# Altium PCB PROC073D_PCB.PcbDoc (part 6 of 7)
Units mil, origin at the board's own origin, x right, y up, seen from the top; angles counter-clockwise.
Board outline 2165.35 x 2695.12 mil, 8 copper layers (Top Layer, L2_GND, L3_SIGNAL 1, L4_SIGNAL 2, L5_SIGNAL 3, L6_SIGNAL 4, L7_GND, Bottom Layer), stack 56.1 mil thick; 414 components, 319 nets, 1353 pads, 1669 vias.
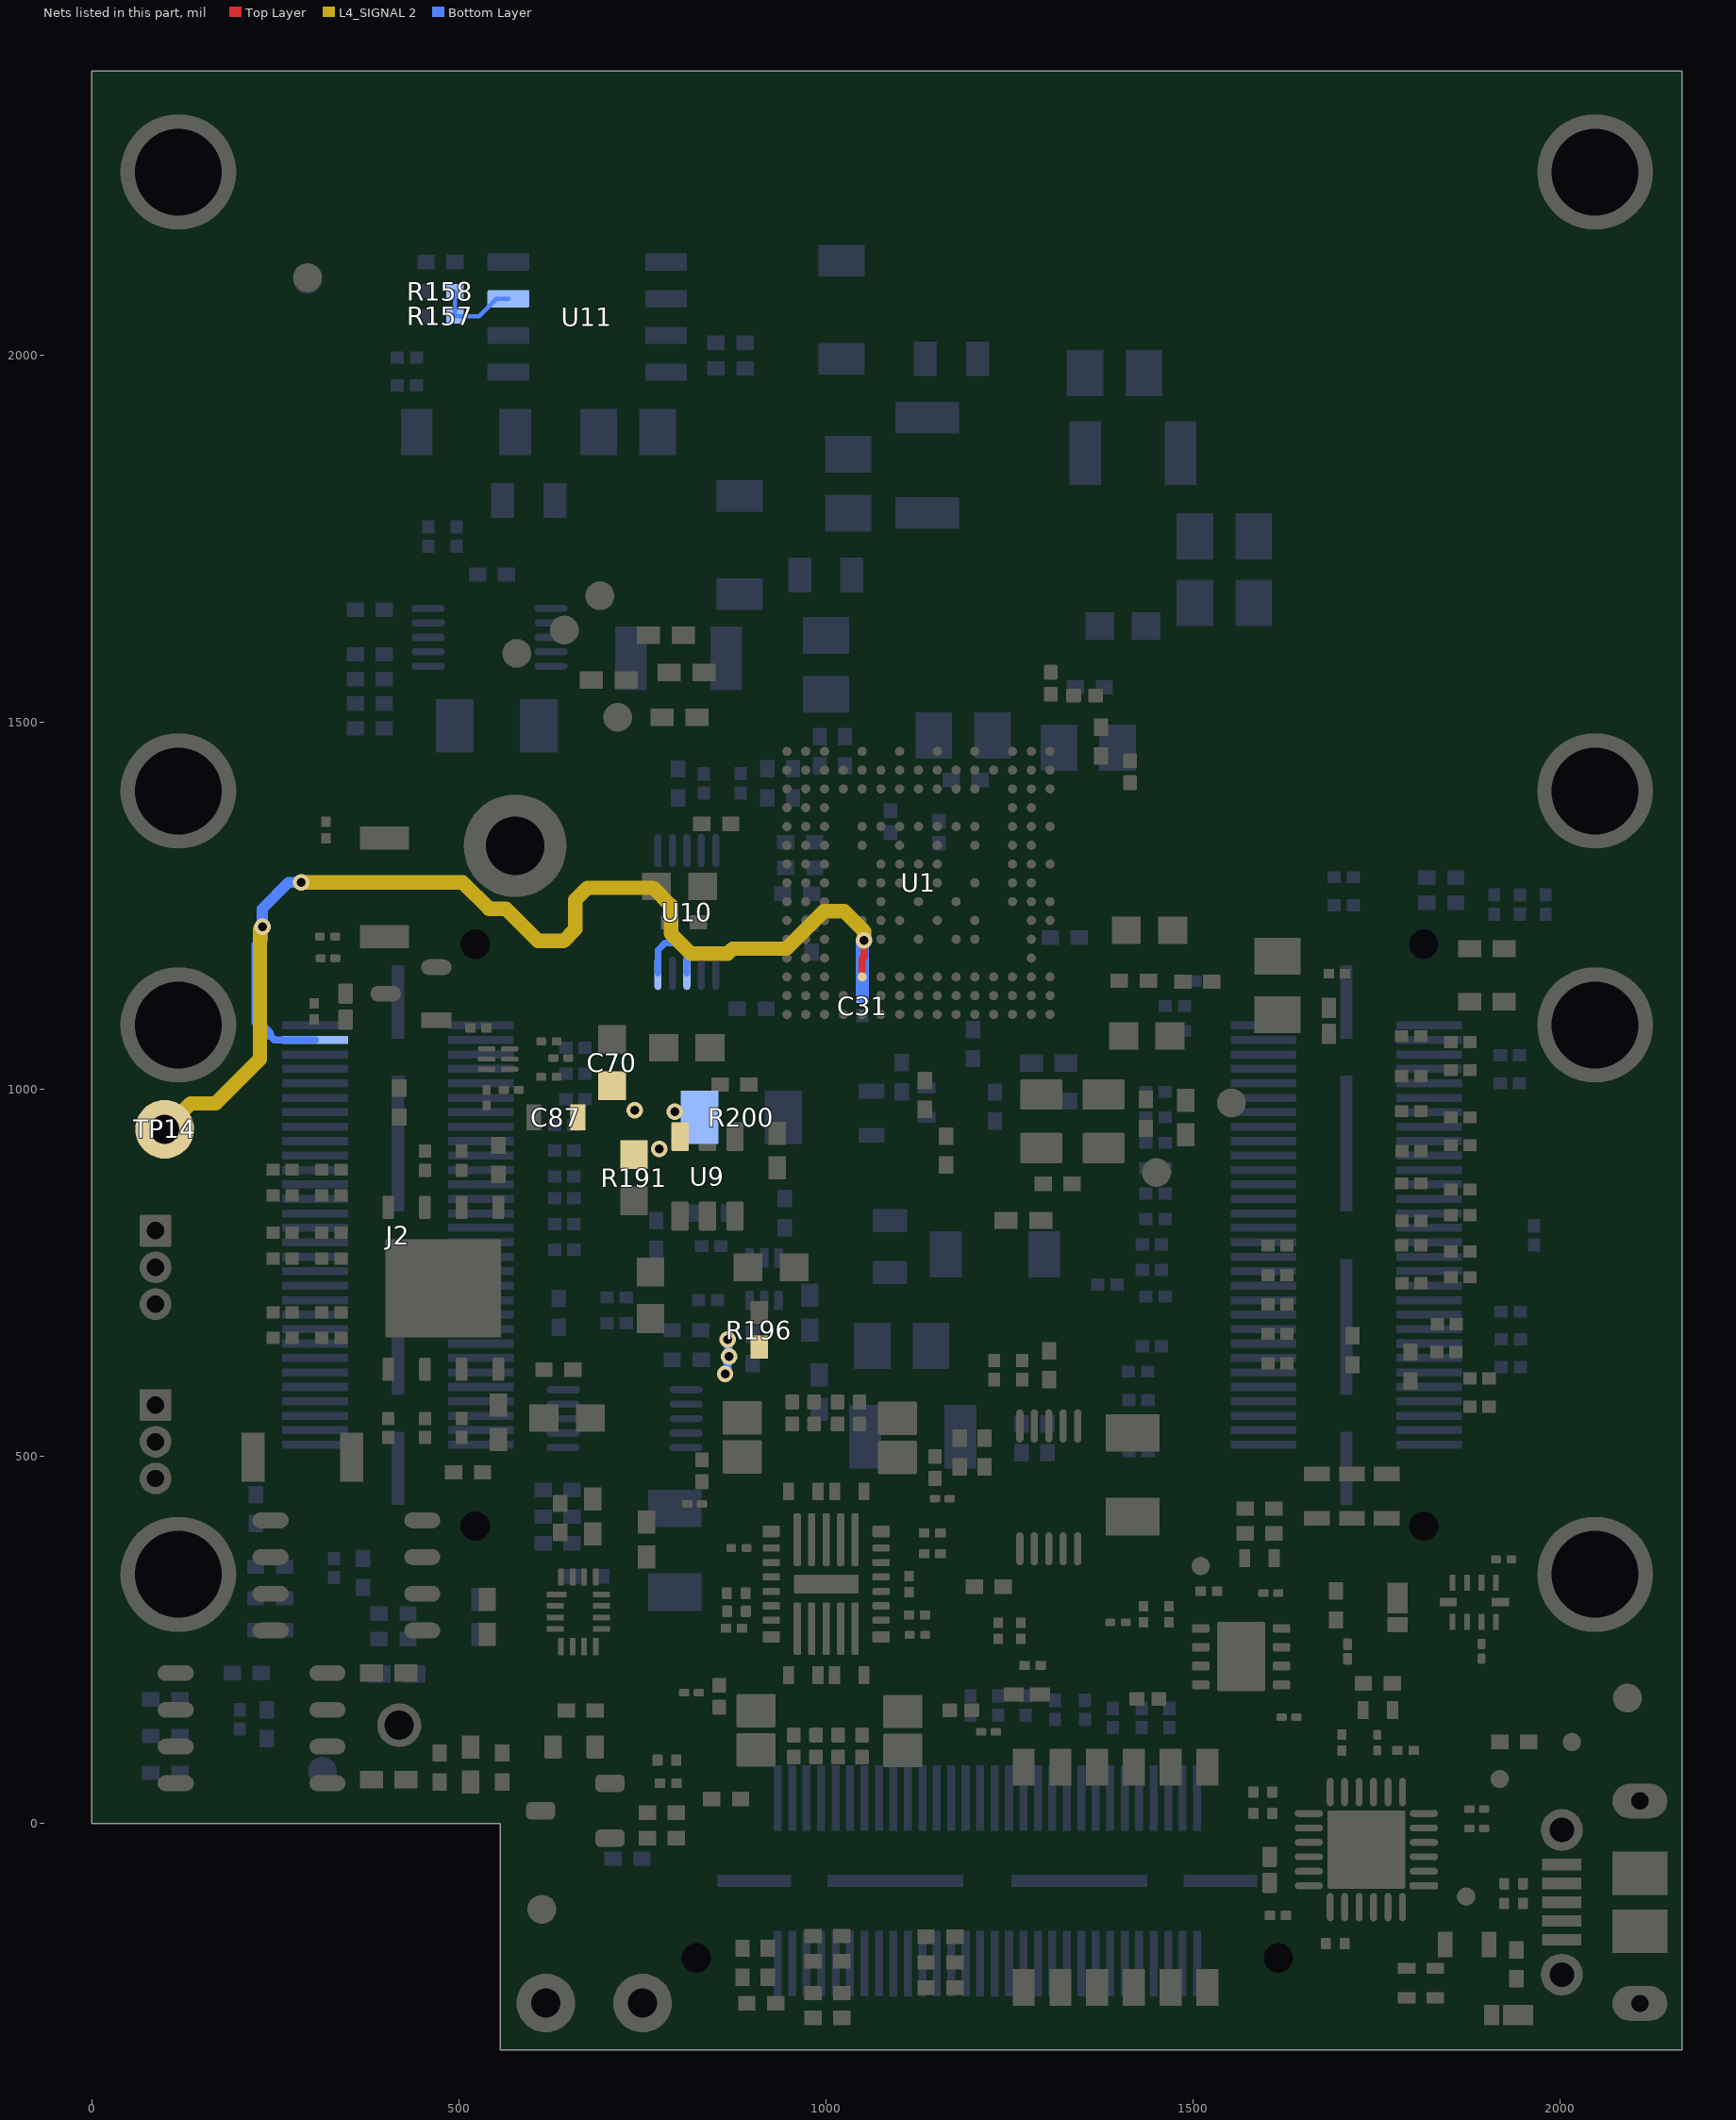
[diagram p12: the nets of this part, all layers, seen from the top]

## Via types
v1: diameter 13.77/15.74 (per signal layer), hole 5.9, Top Layer to L2_GND, tented both sides, 900 vias
v2: diameter 22.4, hole 12.2, Top Layer to Bottom Layer, tented both sides, 509 vias
v3: diameter 13.78/15.75 (per signal layer), hole 5.9, Top Layer to L2_GND, tented both sides, 72 vias
v4: diameter 18, hole 8, Top Layer to Bottom Layer, tented both sides, 71 vias
v5: diameter 22, hole 12.2, Top Layer to Bottom Layer, tented both sides, 57 vias
v6: diameter 25, hole 15, Top Layer to Bottom Layer, tented both sides, 28 vias
v7: diameter 19.68, hole 7.87, Top Layer to Bottom Layer, 16 vias
v8: diameter 13.77/15.74 (per signal layer), hole 5.9, Top Layer to L2_GND, tented top, 15 vias
v9: diameter 13.78/15.75 (per signal layer), hole 5.9, Top Layer to L2_GND, tented top, 1 vias

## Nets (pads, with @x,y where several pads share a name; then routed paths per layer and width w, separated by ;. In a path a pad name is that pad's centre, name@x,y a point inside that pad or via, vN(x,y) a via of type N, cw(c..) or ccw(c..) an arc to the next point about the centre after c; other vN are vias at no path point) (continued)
VCC_LD_SW_3V3: C70.1 C87.2 R191.2 R196.1 R200.1 U9.6 U10.8 U10.10 | length 160.9
  Bottom Layer w9: U10.10@771.22,1157.77 771.22,1189.43 781.22,1199.43 800.59,1199.43 810.59,1189.43 U10.8@810.59,1157.77
  Bottom Layer w12: v2(862.61,612.42) 865.79,615.6 865.79,633.91 v2(868.15,636.27) 867.13,637.29 867.13,658.2 v2(866.15,659.18)
  other v2: 773.12,918.67 794.01,969.55 739.62,971.31
VPP_1P7: C31.2 J2.57 TP14.1 U1.L13 | length 1753.3
  Top Layer w10: U1.L13@1049.21,1153.09 1049.2,1177.77 1052.02,1180.59 v2(1052.02,1202.49)
  L4_SIGNAL 2 w19.68: TP14.1@99.51,945.49 134.85,980.83 169.16,980.83 229.24,1040.91 229.24,1217.81 v2(232.52,1221.08) ; v2(285.39,1281.6) 505.38,1281.6 541.2,1245.78 564.17,1245.78 607.94,1202.01 642.73,1202.01 658.57,1217.85 658.57,1257.88 675.05,1274.36 764.73,1274.36 789.03,1250.06 789.03,1212.15 816.54,1184.65 865.97,1184.65 872.79,1191.47 946.19,1191.47 997.06,1242.33 1024.8,1242.33 1052.02,1215.11 v2(1052.02,1202.49)
  Bottom Layer w10: 241.12,1075.3 249.25,1067.18 J2.57@304.44,1067.18
  Bottom Layer w15: 241.12,1075.3 225,1091.43 225,1196.18 232.52,1203.7 v2(232.52,1221.08) 232.52,1245.87 268.24,1281.6 v2(285.39,1281.6)
  Bottom Layer w18: C31.2@1049.59,1126.42 1049.59,1200.05 v2(1052.02,1202.49)
WP#: R157.1 R158.2 U11.7 | length 117
  Bottom Layer w6: R158.2@494.69,2086.43 R157.1@494.69,2052.43 527.59,2052.43 551.59,2076.43 U11.7@567.72,2076.43
pads on no net: FID1.1 FID2.1 FID3.1 FID4.1 FID5.1 FID6.1 J1.MH1 J1.MH2 J2.1 J2.2 J2.3 J2.4 J2.5 J2.6 J2.7 J2.8 J2.9 J2.10 J2.11 J2.12 J2.13 J2.14 J2.15 J2.16 J2.17 J2.18 J2.20 J2.22 J2.24 J2.26 J2.33 J2.35 J2.45 J2.47 J2.49 J2.51 J2.53 J2.55 J2.MH1 J2.MH2 J5.4 J6.4 J6.5 J6.6 J6.8 J6.14 J6.MH1 J6.MH2 LBL1.0 S1.6 S1.7 U2. U4. U11.1 U11.2 U14.10 U14.11 U14.14 U14.15 U14.16 U14.18 U14.19 U14.21 U14.22 U14.23 U14.24 U16.9@1565.35,202.73 U16.9@1565.35,252.34

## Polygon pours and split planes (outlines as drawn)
GND on Top Layer "GND_L01_P43637" (solid, remove dead copper, pour order 43637): 19 vertices, not listed, extent 1626.69,448.97 1824.73,644.12
VCC_3V3 on Top Layer " " (solid, remove dead copper, pour order 43574): 864.52,29.48 858.08,23.04 818.23,23.04 818.23,87.88 864.52,87.88
PMIC_1V2 on Top Layer "Bottom Layer-PMIC_1V2" (solid, pour order 43628): 1176.88,139.67 1176.88,51.5 1006.53,51.49 1006.53,139.67
PMIC_3V3 on Top Layer "Bottom Layer-PMIC_3V3" (solid, pour order 43625): 17 vertices, not listed, extent 869.49,21.76 996.5,123.71
GND on Top Layer "GND_L01_P43638" (solid, remove dead copper, pour order 43638): 24 vertices, not listed, extent 1134.79,114.97 1434.22,281.92
SW2_CAP on Top Layer "SW2_CAP_L01_P43547" (solid, remove dead copper, pour order 43547): 823.81,445.71 819.76,449.76 819.76,475.41 822.6,478.25 840.37,478.25 843.87,474.75 843.87,428.59 840.67,425.39 826.75,425.39 823.81,428.34
GND on Top Layer "TOP-No Net" (solid, remove dead copper, pour order 43644): 848.74,2365.39 667.78,2365.74 667.7,1749.46 727.62,1689.54 846.06,1689.54 848.74,1692.21
GND on Top Layer "TOP-No Net" (solid, remove dead copper, pour order 43640): 1976.7,2327.43 1976.77,2365.35 809.74,2365.49 809.74,2327.43
GND on Top Layer "TOP-No Net" (solid, remove dead copper, pour order 43645): 1940.79,2365.31 2139.97,2365.71 2140.06,1608.43 1940.79,1608.42
GND on Top Layer "GND_L01_P448" (solid, remove dead copper, pour order 43648): 32 vertices, not listed, extent 31,1195.43 2140.01,2365.48
GND on Top Layer "TOP-No Net 11" (solid, remove dead copper, pour order 43612): 94 vertices, not listed, extent 996.99,1670.75 1095.41,2143.74
GND on Top Layer "TOP-No Net 17" (solid, remove dead copper, pour order 43611): 94 vertices, not listed, extent 1193.85,1670.75 1292.27,2143.74
GND on Top Layer "OUTLINE-No Net" (solid, remove dead copper, pour order 43564): 1787.47,1737.78 1787.47,1682.49 1805.98,1682.49 1805.98,1670.77 1821.73,1670.77 1821.73,1698.24 1803.22,1698.24 1803.22,1722.03 1821.73,1722.03 1821.73,1762.89 1805.98,1762.89 1805.98,1737.78 1787.47,1737.78
TX3 on Top Layer "TOP-RX1 72" (solid, pour order 43525): 1835.62,1941.12 1831.62,1941.12 1831.62,1880.57 1835.62,1880.57 1835.62,1941.12
GND on Top Layer "OUTLINE-No Net" (solid, remove dead copper, pour order 43557): 1894.77,2143.76 1772.47,2143.76 1772.47,2128.01 1894.77,2128.01 1894.77,2143.76
TX3 on Top Layer "TOP-RX1 73" (solid, pour order 43524): 1835.62,2049.7 1831.62,2049.7 1831.62,1989.15 1835.62,1989.15 1835.62,2049.7
GND on Top Layer "TOP-GND 25" (solid, remove dead copper, pour order 43545): 1894.77,1802.26 1845.52,1802.26 1845.52,1786.52 1894.77,1786.52
TX3 on Top Layer "TOP-RX1 74" (solid, pour order 43527): 1837.52,1762.89 1829.73,1762.89 1829.73,1724.7 1837.52,1724.7 1837.52,1762.89
GND on Top Layer "OUTLINE-No Net" (solid, remove dead copper, pour order 43543): 1821.73,1802.26 1772.47,1802.26 1772.47,1786.52 1821.73,1786.52 1821.73,1802.26
TX3 on Top Layer "TOP-RX1 75" (solid, pour order 43513): 1837.52,1724.7 1829.73,1724.7 1829.73,1710.14 1837.52,1710.14 1837.52,1724.7
GND on Top Layer "OUTLINE-No Net" (solid, remove dead copper, pour order 43535): 1821.73,1786.52 1805.98,1786.52 1805.98,1762.89 1821.73,1762.89 1821.73,1786.52
TX3 on Top Layer "TOP-RX1 76" (solid, pour order 43509): 1850.51,1728.6 1837.52,1728.6 1837.52,1720.81 1850.51,1720.81 1850.51,1728.6
GND on Top Layer "TOP-GND 26" (solid, remove dead copper, pour order 43540): 1861.27,1786.52 1845.52,1786.52 1845.52,1762.89 1861.27,1762.89 1861.27,1786.52
TX3 on Top Layer "TOP-RX1 77" (solid, pour order 43567): 1859.21,1880.57 1808.03,1880.57 1808.03,1832.54 1859.21,1832.54 1859.21,1880.57
GND on Top Layer "TOP-GND 27" (solid, remove dead copper, pour order 43554): 1861.27,1762.89 1845.52,1762.89 1845.52,1736.6 1858.51,1736.6 1858.51,1712.81 1845.52,1712.81 1845.52,1670.77 1861.27,1670.77 1861.27,1697.06 1874.26,1697.06 1874.26,1752.35 1861.27,1752.35 1861.27,1762.89
TX3 on Top Layer "TOP-RX1 78" (solid, pour order 43532): 1837.52,1802.26 1829.73,1802.26 1829.73,1762.89 1837.52,1762.89 1837.52,1802.26
TX3 on Top Layer "TOP-RX1 79" (solid, pour order 43514): 1835.62,1832.54 1831.62,1832.54 1831.62,1802.26 1835.62,1802.26 1835.62,1832.54
TX3 on Top Layer "TOP-RX1 80" (solid, pour order 43518): 1829.73,1714.03 1811.22,1714.03 1811.22,1706.24 1829.73,1706.24 1829.73,1714.03
TX3 on Top Layer "TOP-RX1 81" (solid, pour order 43579): 1871.03,1989.15 1796.22,1989.15 1796.22,1941.12 1871.03,1941.12 1871.03,1989.15
GND on Top Layer "OUTLINE-No Net" (solid, remove dead copper, pour order 43589): 1788.22,2128.01 1772.47,2128.01 1772.47,1802.26 1788.22,1802.26 1788.22,2128.01
TX3 on Top Layer "TOP-RX1 83" (solid, pour order 43568): 1859.21,2097.74 1808.03,2097.74 1808.03,2049.7 1859.21,2049.7 1859.21,2097.74
GND on Top Layer "OUTLINE-No Net" (solid, remove dead copper, pour order 43585): 1894.77,2128.01 1879.03,2128.01 1879.03,1802.26 1894.77,1802.26 1894.77,2128.01
GND on Top Layer "OUTLINE-No Net" (solid, remove dead copper, pour order 43590): 1697.92,2226.44 1682.17,2226.44 1682.17,1900.69 1697.92,1900.69 1697.92,2226.44
TX2 on Top Layer "TOP-RX1 83" (solid, pour order 43571): 1662.36,2196.16 1611.18,2196.16 1611.18,2148.13 1662.36,2148.13 1662.36,2196.16
GND on Top Layer "OUTLINE-No Net" (solid, remove dead copper, pour order 43587): 1591.37,2226.44 1575.62,2226.44 1575.62,1900.69 1591.37,1900.69 1591.37,2226.44
TX2 on Top Layer "TOP-RX1 81" (solid, pour order 43578): 1674.17,2087.58 1599.37,2087.58 1599.37,2039.55 1674.17,2039.55 1674.17,2087.58
TX2 on Top Layer "TOP-RX1 80" (solid, pour order 43517): 1632.88,1812.46 1614.37,1812.46 1614.37,1804.66 1632.88,1804.66 1632.88,1812.46
TX2 on Top Layer "TOP-RX1 79" (solid, pour order 43516): 1638.77,1930.96 1634.77,1930.96 1634.77,1900.69 1638.77,1900.69 1638.77,1930.96
TX2 on Top Layer "TOP-RX1 78" (solid, pour order 43531): 1640.67,1900.69 1632.88,1900.69 1632.88,1861.32 1640.67,1861.32 1640.67,1900.69
TX2 on Top Layer "TOP-RX1 77" (solid, pour order 43566): 1662.36,1979 1611.18,1979 1611.18,1930.96 1662.36,1930.96 1662.36,1979
GND on Top Layer "TOP-GND 26" (solid, remove dead copper, pour order 43536): 1664.42,1884.94 1648.67,1884.94 1648.67,1861.32 1664.42,1861.32 1664.42,1884.94
TX2 on Top Layer "TOP-RX1 76" (solid, pour order 43508): 1653.66,1827.03 1640.67,1827.03 1640.67,1819.23 1653.66,1819.23 1653.66,1827.03
GND on Top Layer "OUTLINE-No Net" (solid, remove dead copper, pour order 43538): 1624.88,1884.94 1609.13,1884.94 1609.13,1861.32 1624.88,1861.32 1624.88,1884.94
TX2 on Top Layer "TOP-RX1 75" (solid, pour order 43512): 1640.67,1823.13 1632.88,1823.13 1632.88,1808.56 1640.67,1808.56 1640.67,1823.13
GND on Top Layer "OUTLINE-No Net" (solid, remove dead copper, pour order 43542): 1624.88,1900.69 1575.62,1900.69 1575.62,1884.94 1624.88,1884.94 1624.88,1900.69
TX2 on Top Layer "TOP-RX1 74" (solid, pour order 43526): 1640.67,1861.32 1632.88,1861.32 1632.88,1823.13 1640.67,1823.13 1640.67,1861.32
GND on Top Layer "TOP-GND 25" (solid, remove dead copper, pour order 43546): 1697.92,1900.69 1648.67,1900.69 1648.67,1884.94 1697.92,1884.94 1697.92,1900.69
TX2 on Top Layer "TOP-RX1 73" (solid, pour order 43520): 1638.77,2148.13 1634.77,2148.13 1634.77,2087.58 1638.77,2087.58 1638.77,2148.13
GND on Top Layer "OUTLINE-No Net" (solid, remove dead copper, pour order 43556): 1697.92,2242.18 1575.62,2242.18 1575.62,2226.44 1697.92,2226.44 1697.92,2242.18
TX2 on Top Layer "TOP-RX1 72" (solid, pour order 43522): 1638.77,2039.55 1634.77,2039.55 1634.77,1979 1638.77,1979 1638.77,2039.55
GND on Top Layer "OUTLINE-No Net" (solid, remove dead copper, pour order 43563): 1393.77,1737.78 1393.77,1682.49 1412.28,1682.49 1412.28,1670.77 1428.03,1670.77 1428.03,1698.24 1409.52,1698.24 1409.52,1722.03 1428.03,1722.03 1428.03,1762.89 1412.28,1762.89 1412.28,1737.78 1393.77,1737.78
TX1 on Top Layer "TOP-RX1 72" (solid, pour order 43523): 1441.92,1941.12 1437.92,1941.12 1437.92,1880.57 1441.92,1880.57 1441.92,1941.12
GND on Top Layer "OUTLINE-No Net" (solid, remove dead copper, pour order 43558): 1501.07,2143.76 1378.77,2143.76 1378.77,2128.01 1501.07,2128.01 1501.07,2143.76
TX1 on Top Layer "TOP-RX1 73" (solid, pour order 43521): 1441.92,2049.7 1437.92,2049.7 1437.92,1989.15 1441.92,1989.15 1441.92,2049.7
GND on Top Layer "TOP-GND 25" (solid, remove dead copper, pour order 43544): 1501.07,1802.26 1451.82,1802.26 1451.82,1786.52 1501.07,1786.52 1501.07,1802.26
TX1 on Top Layer "TOP-RX1 74" (solid, pour order 43528): 1443.82,1762.89 1436.03,1762.89 1436.03,1724.7 1443.82,1724.7 1443.82,1762.89
GND on Top Layer "OUTLINE-No Net" (solid, remove dead copper, pour order 43541): 1428.03,1802.26 1378.77,1802.26 1378.77,1786.52 1428.03,1786.52 1428.03,1802.26
TX1 on Top Layer "TOP-RX1 75" (solid, pour order 43511): 1443.82,1724.7 1436.03,1724.7 1436.03,1710.14 1443.82,1710.14 1443.82,1724.7
GND on Top Layer "OUTLINE-No Net" (solid, remove dead copper, pour order 43537): 1428.03,1786.52 1412.28,1786.52 1412.28,1762.89 1428.03,1762.89 1428.03,1786.52
TX1 on Top Layer "TOP-RX1 76" (solid, pour order 43510): 1456.81,1728.6 1443.82,1728.6 1443.82,1720.81 1456.81,1720.81 1456.81,1728.6
GND on Top Layer "TOP-GND 26" (solid, remove dead copper, pour order 43539): 1467.57,1786.52 1451.82,1786.52 1451.82,1762.89 1467.57,1762.89 1467.57,1786.52
TX1 on Top Layer "TOP-RX1 77" (solid, pour order 43569): 1465.51,1880.57 1414.33,1880.57 1414.33,1832.54 1465.51,1832.54 1465.51,1880.57
GND on Top Layer "TOP-GND 27" (solid, remove dead copper, pour order 43555): 1467.57,1762.89 1451.82,1762.89 1451.82,1736.6 1464.81,1736.6 1464.81,1712.81 1451.82,1712.81 1451.82,1670.77 1467.57,1670.77 1467.57,1697.06 1480.56,1697.06 1480.56,1752.35 1467.57,1752.35 1467.57,1762.89
TX1 on Top Layer "TOP-RX1 78" (solid, pour order 43530): 1443.82,1802.26 1436.03,1802.26 1436.03,1762.89 1443.82,1762.89 1443.82,1802.26
TX1 on Top Layer "TOP-RX1 79" (solid, pour order 43515): 1441.92,1832.54 1437.92,1832.54 1437.92,1802.26 1441.92,1802.26 1441.92,1832.54
TX1 on Top Layer "TOP-RX1 80" (solid, pour order 43519): 1436.03,1714.03 1417.52,1714.03 1417.52,1706.24 1436.03,1706.24 1436.03,1714.03
TX1 on Top Layer "TOP-RX1 81" (solid, pour order 43580): 1477.32,1989.15 1402.52,1989.15 1402.52,1941.12 1477.32,1941.12 1477.32,1989.15
GND on Top Layer "OUTLINE-No Net" (solid, remove dead copper, pour order 43586): 1394.52,2128.01 1378.77,2128.01 1378.77,1802.26 1394.52,1802.26 1394.52,2128.01
TX1 on Top Layer "TOP-RX1 83" (solid, pour order 43570): 1465.51,2097.74 1414.33,2097.74 1414.33,2049.7 1465.51,2049.7 1465.51,2097.74
GND on Top Layer "OUTLINE-No Net" (solid, remove dead copper, pour order 43588): 1501.07,2128.01 1485.32,2128.01 1485.32,1802.26 1501.07,1802.26 1501.07,2128.01
GND on Top Layer "TOP-No Net 10" (solid, remove dead copper, pour order 43613): 94 vertices, not listed, extent 1095.42,1670.75 1193.84,2143.74
GND on Top Layer "TOP-No Net 23" (solid, remove dead copper, pour order 43623): 125 vertices, not listed, extent 891.67,1670.75 996.98,2143.74
GND on Top Layer "TOP-No Net 24" (solid, pour order 43550): 35 vertices, not listed, extent 1292.28,1786.55 1299.17,2143.74
RX1 on Top Layer "TOP-No Net 43" (solid, remove dead copper, pour order 43620): 38 vertices, not listed, extent 910.37,1670.75 985.17,2097.72
RX2 on Top Layer "TOP-No Net 42" (solid, remove dead copper, pour order 43617): 38 vertices, not listed, extent 1008.8,1670.75 1083.6,2097.72
RX3 on Top Layer "TOP-No Net 41" (solid, remove dead copper, pour order 43618): 38 vertices, not listed, extent 1107.23,1670.75 1182.03,2097.72
RX4 on Top Layer "TOP-No Net 40" (solid, remove dead copper, pour order 43619): 38 vertices, not listed, extent 1205.66,1670.75 1280.46,2097.72
TX1 on Top Layer "TOP-RX1 82" (solid, remove dead copper, pour order 43534): 1443.82,1710.14 1436.03,1710.14 1436.03,1670.77 1443.82,1670.77 1443.82,1710.14
GND on Top Layer "OUTLINE-No Net" (solid, remove dead copper, pour order 43562): 1590.62,1836.21 1590.62,1780.92 1609.13,1780.92 1609.13,1769.19 1624.88,1769.19 1624.88,1796.66 1606.37,1796.66 1606.37,1820.46 1624.88,1820.46 1624.88,1861.32 1609.13,1861.32 1609.13,1836.21 1590.62,1836.21
GND on Top Layer "TOP-GND 27" (solid, remove dead copper, pour order 43553): 1664.42,1861.32 1648.67,1861.32 1648.67,1835.03 1661.66,1835.03 1661.66,1811.23 1648.67,1811.23 1648.67,1769.19 1664.42,1769.19 1664.42,1795.48 1677.41,1795.48 1677.41,1850.77 1664.42,1850.77 1664.42,1861.32
TX2 on Top Layer "TOP-RX1 82" (solid, remove dead copper, pour order 43533): 1640.67,1808.56 1632.88,1808.56 1632.88,1769.19 1640.67,1769.19 1640.67,1808.56
TX3 on Top Layer "TOP-RX1 82" (solid, remove dead copper, pour order 43529): 1837.52,1710.14 1829.73,1710.14 1829.73,1670.77 1837.52,1670.77 1837.52,1710.14
PMICOUT_3V3 on Top Layer "PMICOUT_3V3_L01_P43548" (solid, remove dead copper, pour order 43548): 1888.11,267 1884.01,262.9 1884.01,240.03 1890.12,233.93 1918.25,233.93 1923.94,239.61 1923.94,251.86 1913.18,262.62 1906,262.62 1896.94,271.69 1896.94,287.72 1888.11,287.72
GND on Top Layer "GND_L01_P43647" (solid, remove dead copper, pour order 43647): 17 vertices, not listed, extent 30,241.44 226,2365.43
VCC_3V3 on Top Layer "TOP-No Net 1" (solid, remove dead copper, pour order 43646): 49 vertices, not listed, extent 41.47,164.01 885.63,871.43
CONN_5V on Top Layer "CONN_5V_L01_P43643" (solid, remove dead copper, pour order 43643): 1070.98,23.91 1087.57,40.5 1238.25,40.5 1249.82,28.92 1570.7,28.92 1604.25,-4.63 1604.25,-153.18 1564.44,-192.99 1380.08,-192.99 1330.58,-143.49 1251.49,-143.49 1206.02,-98.02 1081.74,-98.02 1070.98,-87.26
GND on Top Layer "TOP-No Net 1" (solid, remove dead copper, pour order 43642): 43 vertices, not listed, extent 573.85,531.61 806.04,1124.49
CB_PMIC_1V8 on Top Layer "CB_PMIC_1V8_L01_P43641" (solid, remove dead copper, pour order 43641): 21 vertices, not listed, extent 1305.39,336.57 1707.37,617.51
PMICOUT_3V3 on Top Layer "PMICOUT_3V3_L01_P43639" (solid, remove dead copper, pour order 43639): 26 vertices, not listed, extent 1236.39,31.5 1710.68,184.93
CONN_5V on Top Layer "CONN_5V_L01_P43636" (solid, remove dead copper, pour order 43636): 24 vertices, not listed, extent 1593.74,258.91 1865.7,505.35
PMIC_1V8 on Top Layer "Bottom Layer-PMIC_1V8" (solid, pour order 43635): 1004.7,631.77 1041.77,631.77 1044.89,632.39 1047.54,634.16 1073.58,660.2 1168.05,660.2 1189.28,638.97 1189.28,529.14 1068.83,529.14 1068.83,562.56 1004.71,562.56 1004.71,577.43
5V_IN_USB on Top Layer "5V_IN_USB_L01_P43634" (solid, remove dead copper, pour order 43634): 1867.12,-213.4 1887,-193.52 1902.36,-193.52 1914.38,-205.54 1914.38,-276.86 1906.59,-284.65 1679.89,-284.64 1664.98,-269.73 1664.98,-217.76 1678.81,-203.93 1761.64,-203.93 1771.11,-213.4
VCC_LD_SW_3V3 on Top Layer "TOP-No Net 1" (solid, remove dead copper, pour order 43633): 650.73,926.93 656.93,920.73 691.29,920.73 721,891.01 788.48,891.43 788.74,891.43 813.74,916.43 813.74,981.43 767.73,1027.43 699.86,1027.43 692.38,1027.43 688.12,1023.17 688.12,1019.79 650.73,982.41
PMIC_1V8 on Top Layer "PMIC_1V8_L01_P43632" (solid, remove dead copper, pour order 43632): 17 vertices, not listed, extent 1289.77,309.21 1467.93,446.98
5V_IN on Top Layer "5V_IN_L01_P43631" (solid, remove dead copper, pour order 43631): 1740.81,277.63 1759.01,277.63 1762.6,281.23 1807.5,281.23 1814.93,273.79 1814.93,265.95 1882.75,198.14 1882.75,114.29 1858.8,90.35 1793.3,90.35 1793.3,206.45 1786.92,212.82 1780.53,212.82 1735.06,258.29 1735.06,271.88
GND on Top Layer "GND_L01_P43630" (solid, remove dead copper, pour order 43630): 22 vertices, not listed, extent 1417.13,267.2 1599.4,441.68
VCC_3V3 on Top Layer "VCC_3V3_L01_P43629" (solid, remove dead copper, pour order 43629): 1340.16,489.06 1326.68,475.58 1319.13,475.58 1275.32,431.77 1275.32,298.96 1263.73,287.38 1225.53,287.38 1200.79,312.12 1200.79,433.18 1243.32,475.71 1261.59,475.71 1292.95,507.07 1331.99,507.07 1340.16,498.9
PMICOUT_3V3 on Top Layer "PMICOUT_3V3_L01_P43627" (solid, remove dead copper, pour order 43627): 23 vertices, not listed, extent 1773.63,-11.61 1930.87,123.6
RADAR_1V8 on Top Layer "RADAR_1V8_L01_P222" (solid, remove dead copper, pour order 43626): 1555.96,1145.13 1544.3,1133.47 1544.3,1025.55 1555,1014.86 1635.01,1014.86 1648.55,1028.4 1648.55,1134.62 1637.41,1145.76 1590.66,1145.76 1581.98,1154.44 1565.27,1154.44
GND on Top Layer "GND_L01_P43609" (solid, remove dead copper, pour order 43609): 768.37,462.69 795.41,462.69 818.07,440.03 818.07,406.97 798.29,387.19 743.62,387.19 717.6,413.21 678.02,413.21 666.84,424.39 666.84,459.36 670.16,462.69 708.16,462.69
GND on Top Layer "GND_L01_P43624" (solid, remove dead copper, pour order 43624): 17 vertices, not listed, extent 902.31,-202.93 1002.96,-54.09
NetR214_1 on Top Layer "NETR214_1_L01_P43622" (solid, remove dead copper, pour order 43622): 428.73,1249.13 340.26,1249.13 324.8,1233.67 324.8,1162.7 332.41,1155.09 423.15,1155.09 453.32,1185.26 453.32,1224.54
RADAR_VOUT_PA on Top Layer "TOP-No Net 1" (solid, remove dead copper, pour order 43621): 17 vertices, not listed, extent 1271.59,1427.43 1487.53,1544.31
5V_IN_USB on Top Layer "5V_IN_USB_L01_P43615" (solid, remove dead copper, pour order 43615): 20 vertices, not listed, extent 1602.23,132.6 1748.39,223.68
GND on Top Layer "GND_L01_P43614" (solid, remove dead copper, pour order 43614): 25 vertices, not listed, extent 1421.57,1010.72 1540.44,1163.61
SW2 on Top Layer "SW2_L01_P43616" (solid, remove dead copper, pour order 43616): 22 vertices, not listed, extent 817.41,348.65 991.46,524.42
PMIC_1V0 on Top Layer "Bottom Layer-PMIC_1V0 1" (solid, pour order 43610): 859.51,529.47 854.25,534.73 854.25,573.32 862.16,581.22 882.1,581.22 942.1,641.22 979.5,641.22 994.13,626.6 994.13,563.34 929.66,563.34 929.66,529.47
RADAR_1V2 on Top Layer "RADAR_1V2_L01_P43608" (solid, remove dead copper, pour order 43608): 955.59,1056.43 910.59,1056.43 860.59,1106.43 830.02,1106.43 820.45,1096.86 820.45,1036.57 820.59,1036.43 875.58,1036.43 885.59,1026.42 885.59,991.43 930.59,991.43 970.59,1031.43 970.59,1041.43
CB_PMIC_1V8 on Top Layer "CB_PMIC_1V8_L01_P43607" (solid, remove dead copper, pour order 43607): 937.54,779.59 982.29,779.59 1004.99,802.29 1030.12,802.29 1056.78,775.63 1056.78,744.44 1020.6,708.26 948.89,708.26 933.18,723.97 933.18,775.22
RADAR_1V8 on Top Layer "RADAR_1V8_L01_P43606" (solid, remove dead copper, pour order 43606): 1073.04,671.2 1099.31,671.2 1111.97,683.86 1111.97,719.66 1094.42,737.21 1062.37,737.21 1025.01,699.84 977.34,699.84 971.59,694.09 971.59,664.23 995.89,639.93 1041.77,639.93
5V_IN on Top Layer "5V_IN_L01_P43605" (solid, remove dead copper, pour order 43605): 17 vertices, not listed, extent 1251.55,208.05 1362.06,321.63
SW1 on Top Layer "SW1_L01_P43602" (solid, remove dead copper, pour order 43602): 29 vertices, not listed, extent 1012.88,130.42 1181.38,303.16
NetD2_2 on Top Layer "NETD2_2_L01_P43601" (solid, remove dead copper, pour order 43601): 1789.55,346.9 1799.66,336.79 1799.66,290.77 1795.39,286.5 1736.91,286.5 1721.99,301.41 1682.72,301.41 1679.57,304.57 1679.57,329.59 1696.88,346.9
RADAR_3V3 on Top Layer "RADAR_3V3_L01_P43600" (solid, remove dead copper, pour order 43600): 1862.02,1209.2 1848.53,1195.71 1848.53,1150.56 1826.05,1128.08 1826.05,1112.64 1839.93,1098.76 1893.68,1098.76 1899.56,1104.64 1899.56,1197.85 1888.21,1209.2
GND on Top Layer " " (solid, remove dead copper, pour order 43604): 19 vertices, not listed, extent 943.16,109.15 1062.47,237.32
5V_IN_SW on Top Layer "5V_IN_SW_L01_P43599" (solid, remove dead copper, pour order 43599): 1691.83,229.94 1698.96,237.08 1716.63,237.08 1727.97,248.42 1727.97,285.56 1717.2,296.33 1666.86,296.33 1641.76,271.23 1641.76,260.13 1638.49,256.87 1608.96,256.87 1601.18,249.08 1601.18,232.75 1603.99,229.94
GND on Top Layer "GND_L01_P43597" (solid, remove dead copper, pour order 43597): 1778.66,-205.06 1770.59,-196.98 1770.59,-159.85 1784.34,-146.1 1856.21,-146.1 1878.72,-168.61 1878.72,-192.58 1866.24,-205.06
PMIC_1V0 on Top Layer "PMIC_1V0_L01_P43596" (solid, remove dead copper, pour order 43596): 642.15,1156.3 607.54,1156.3 576.31,1125.07 576.31,1079 578.98,1076.34 623.94,1076.34 644.29,1096.69 665.12,1096.69 671.4,1102.97 671.4,1127.06
VCC_LD_SW_3V3 on Top Layer "VCC_LD_SW_3V3_L01_P43595" (solid, remove dead copper, pour order 43595): 922.03,678.09 936.86,663.26 936.86,646.17 884.73,594.03 852.65,594.03 846.54,600.14 846.54,665.79 852.87,672.12 880.04,672.12 886.02,678.09
GND on Top Layer "GND_L01_P43594" (solid, remove dead copper, pour order 43594): 23 vertices, not listed, extent 1701.54,87.45 1785.19,237.53
RADAR_3V3 on Top Layer "RADAR_3V3_L01_P220" (solid, remove dead copper, pour order 43593): 815,1296.43 815,1216.43 820,1211.43 900,1211.43 905,1216.43 905,1231.43 890,1246.43 885,1246.43 865,1266.43 865,1286.43 855,1296.43
USB_5V on Top Layer "USB_5V_L01_P43592" (solid, remove dead copper, pour order 43592): 1947.75,-132.11 1949.37,-132.11 1965.92,-148.66 2030.56,-148.66 2032.53,-150.63 2032.53,-165.73 2023.29,-174.97 1973.84,-174.97 1962.11,-186.7 1922.78,-186.7 1894.46,-186.7 1891.31,-183.55 1891.31,-147.74 1906.94,-132.11
GND on Top Layer " " (solid, remove dead copper, pour order 43603): 17 vertices, not listed, extent 943.18,437.16 1064.8,554.69
CB_PMIC_1V2 on Top Layer "CB_PMIC_1V2_L01_P43584" (solid, remove dead copper, pour order 43584): 768.23,228.98 768.23,269.75 783.81,285.33 818.53,285.32 837.04,266.82 837.04,218.81 824.54,206.31 790.9,206.31
SW0 on Top Layer "SW0_L01_P43591" (solid, remove dead copper, pour order 43591): 856.67,128.77 933.07,128.77 941.67,137.37 951.5,137.37 956.17,142.04 956.17,173.14 951.44,177.87 854.68,177.87 844.23,167.42 844.23,141.21
SW3 on Top Layer "SW3_L01_P43598" (solid, remove dead copper, pour order 43598): 1160.9,523.32 1163.29,520.92 1163.29,489.55 1160.33,486.59 1140.57,486.59 1129.78,475.8 1045.18,475.8 1039.2,469.81 1033.39,469.81 1025.53,477.67 1034.92,487.06 1034.92,521.78 1036.46,523.32
NetD1_2 on Top Layer "NETD1_2_L01_P43583" (solid, remove dead copper, pour order 43583): 1921.66,-199.32 1926.04,-194.95 1957.45,-194.95 1965.43,-202.93 1965.43,-224.66 1965.43,-274.88 1955.56,-284.75 1926.57,-284.75 1921.66,-279.83
RADAR_1V2 on Top Layer "RADAR_1V2_L01_P43582" (solid, remove dead copper, pour order 43582): 1154.28,1110.21 1123.94,1110.21 1119.59,1105.85 1119.59,1044.37 1124.49,1039.47 1124.49,999.65 1127.52,996.62 1144.62,996.62 1148.02,1000.02 1148.02,1036.07 1158.76,1046.81 1158.76,1105.73
PMIC_1V8 on Top Layer "PMIC_1V8_L01_P43581" (solid, remove dead copper, pour order 43581): 1099.99,440.58 1099.99,460.5 1106.84,467.35 1120.9,467.35 1130.7,457.55 1130.7,422.86 1118.69,410.85 1118.69,407.49 1099.21,388 1086.69,388 1058.11,388 1052.76,393.35 1052.76,421.14 1057.45,425.82 1085.23,425.82
PMIC_1V2 on Top Layer "PMIC_1V2_L01_P43577" (solid, remove dead copper, pour order 43577): 1139.48,232.53 1139.48,214.1 1123.32,197.93 1110.34,197.93 1078.63,229.65 1056.8,229.65 1054.28,232.16 1054.28,262.33 1057.76,265.81 1087.16,265.81 1101.79,251.19 1120.83,251.19
RADAR_1P0_RF1 on Top Layer "RADAR_1P0_RF1_L01_P43576" (solid, remove dead copper, pour order 43576): 1088.54,1386.58 1088.54,1357.15 1095.67,1350.02 1154.94,1350.02 1169.31,1364.39 1169.31,1384.23 1160,1393.54 1129.8,1393.54 1095.49,1393.54
PMIC_1V0 on Top Layer "PMIC_1V0_L01_P43575" (solid, remove dead copper, pour order 43575): 943.44,423.19 922.11,423.19 898.29,447.01 892.66,452.64 877.96,452.64 873.84,448.53 873.84,416.01 900.85,389.01 943.74,389.01 946.06,391.32 946.06,420.57
RADAR_3V3 on Top Layer "RADAR_3V3_L01_P210" (solid, remove dead copper, pour order 43573): 1102.98,954.43 1157,954.43 1169,954.43 1174,949.43 1174,927.43 1171,924.42 1148,924.43 1133.18,909.6 1111.82,909.6 1094,927.43 1094,945.44
RADAR_1P0_RF2 on Top Layer "RADAR_1P0_RF2_L01_P43572" (solid, remove dead copper, pour order 43572): 1273.87,1548.69 1347,1548.69 1348.59,1547.1 1348.59,1519.88 1346.36,1517.65 1304.64,1517.65 1281.16,1494.17 1245.52,1494.17 1245.52,1520.34
5V_IN on Top Layer "5V_IN_L01_P43565" (solid, remove dead copper, pour order 43565): 955.33,220.64 907.23,220.64 907.23,179.64 956.33,179.64 958.33,181.64 958.33,217.64
5V_IN on Top Layer "5V_IN_L01_P43561" (solid, remove dead copper, pour order 43561): 1094.3,472.64 1044.33,472.64 1042.33,470.64 1042.33,434.64 1045.33,431.64 1079.88,431.64 1094.3,446.07
5V_IN on Top Layer "5V_IN_L01_P43560" (solid, remove dead copper, pour order 43560): 1042.33,220.14 1044.33,222.14 1074.6,222.14 1095.45,201.29 1095.45,188.93 1087.66,181.14 1045.33,181.14 1042.33,184.14
5V_IN on Top Layer "5V_IN_L01_P43559" (solid, remove dead copper, pour order 43559): 907.19,461.16 917.17,471.14 955.33,471.14 958.33,468.14 958.33,432.14 957.11,430.92 922.59,430.92 907.19,446.31
5V_IN on Top Layer "5V_IN_L01_P43552" (solid, remove dead copper, pour order 43552): 1063.13,342.66 1088.83,342.66 1098.07,351.91 1143.16,351.91 1145.98,349.09 1145.98,334.33 1140.06,328.41 1129.03,328.41 1127.23,330.21 1098.54,330.21 1097.76,329.44 1060.14,329.44 1060.14,339.67
CONN_5V on Top Layer "CONN_5V_L01_P43551" (solid, remove dead copper, pour order 43551): 1376.03,275.8 1373.52,273.29 1373.52,222.95 1377.93,218.53 1390.72,218.53 1398.96,226.77 1398.96,279.25 1395.12,283.1 1383.32,283.1
RADAR_1V2 on Top Layer "RADAR_1V2_L01_P43549" (solid, remove dead copper, pour order 43549): 17 vertices, not listed, extent 987.42,1181.81 1034.71,1229.05
no net on Top Layer "NONET_L01_P43507" (solid, remove dead copper, pour order 43507): 1057.72,426.56
GND on L3_SIGNAL 1 "GND_L03_P3050" (solid, remove dead copper, pour order 43656): 1013.99,1325.44 1079,1260.43 1079,1237.87 1166.44,1150.43 1407.26,1150.43 1491.25,1234.43 1619.2,1234.43 1710,1325.23 1710,1643.43 1620,1733.43 1089,1733.43 1013.99,1658.42
RADAR_1V2 on L3_SIGNAL 1 "RADAR_1V2_L03_P2940" (solid, remove dead copper, pour order 43654): 20 vertices, not listed, extent 551.25,1014.85 1182.89,1798.17
CB_PMIC_1V2 on L3_SIGNAL 1 "CB_PMIC_1V2_L03_P43657" (solid, remove dead copper, pour order 43657): 37 vertices, not listed, extent 201.84,180.35 904.55,2061.07
5V_IN on L3_SIGNAL 1 "5V_IN_L03_P43655" (solid, remove dead copper, pour order 43655): 64 vertices, not listed, extent 1595.67,-288.68 2097.36,562.1
5V_IN on L3_SIGNAL 1 "5V_IN_L03_P43653" (solid, remove dead copper, pour order 43653): 1173.02,529.73 1350.76,352 1350.76,63.74 1287.17,0.16 1052.43,0.16 906.65,145.94 906.65,509.83 926.54,529.73
GND on L3_SIGNAL 1 "RADAR_1V8_L01_P-001" (solid, remove dead copper, pour order 43658): 27 vertices, not listed, extent 30,241.29 2140,2365.43
CONN_5V on L3_SIGNAL 1 "CONN_5V_L03_P43652" (solid, remove dead copper, pour order 43652): 897.63,-292.84 897.64,-181.25 716.39,0 622.01,0 604.95,-17.07 604.95,-244.79 652.99,-292.83
5V_IN_SW on L3_SIGNAL 1 "5V_IN_SW_L03_P43650" (solid, remove dead copper, pour order 43650): 1563.08,336.12 1587.17,336.12 1614.23,309.06 1717.52,309.06 1738.83,287.75 1738.83,277.83 1723.15,262.16 1690.74,229.75 1619.66,229.75 1579.34,270.07 1568.83,270.07 1548.68,290.22 1548.68,321.72
CONN_5V on L3_SIGNAL 1 "CONN_5V_L03_P43651" (solid, remove dead copper, pour order 43651): 17 vertices, not listed, extent 1604.16,328.42 1859.54,514.57
GND on L5_SIGNAL 3 "GND_L05_P43667" (solid, remove dead copper, pour order 43667): 37 vertices, not listed, extent 1148.42,-281.09 1865.97,1095.13
5V_IN on L5_SIGNAL 3 "5V_IN_L05_P43669" (solid, remove dead copper, pour order 43669): 35 vertices, not listed, extent 570.57,-282.08 1366.8,330.39
VCC_3V3 on L5_SIGNAL 3 "VCC_3V3_L05_P43663" (solid, remove dead copper, pour order 43663): 36 vertices, not listed, extent 421.53,30.28 864.44,1097.13
CB_PMIC_1V8 on L5_SIGNAL 3 "CB_PMIC_1V8_L05_P43664" (solid, remove dead copper, pour order 43664): 37 vertices, not listed, extent 895.66,323.82 1700.13,798.31
5V_IN_USB on L5_SIGNAL 3 "5V_IN_USB_L05_P43665" (solid, remove dead copper, pour order 43665): 1966.61,118.31 2027.61,118.31 2082.92,62.99 2082.92,-282.08 1569.35,-282.08 1569.35,86.01 1640.74,157.4 1640.74,212.24 1689.42,260.93 1764.88,336.39 1871.75,336.39 1950.75,257.38 1950.75,134.16
VCC_3V3 on L5_SIGNAL 3 "VCC_3V3_L04_P2992" (solid, remove dead copper, pour order 43668): 22 vertices, not listed, extent 260.99,1360.21 891.28,2040.52
CONN_5V on L5_SIGNAL 3 "CONN_5V_L05_P43670" (solid, remove dead copper, pour order 43670): 32 vertices, not listed, extent 162.19,-154.93 712.31,1215.35
GND on L5_SIGNAL 3 "BOTTOM-No Net" (solid, remove dead copper, pour order 43671): 33 vertices, not listed, extent 30,241.43 2140,2365.43
RADAR_1V8 on L5_SIGNAL 3 "RADAR_1V8_L04_P3008" (solid, remove dead copper, pour order 43666): 22 vertices, not listed, extent 882.65,1046.43 1596.06,1571.37
PMIC_1V0 on L5_SIGNAL 3 "PMIC_1V0_L04_P2966" (solid, remove dead copper, pour order 43662): 19 vertices, not listed, extent 379.32,1041.14 695.15,1608.33
RADAR_1V2 on L5_SIGNAL 3 "RADAR_1V2_L05_P43661" (solid, remove dead copper, pour order 43661): 21 vertices, not listed, extent 755.06,1015.76 1039.56,1398.23
VCC_3V3 on L5_SIGNAL 3 "VCC_3V3_L05_P43660" (solid, remove dead copper, pour order 43660): 844.59,689.34 858.31,675.62 908.64,675.62 957.85,724.83 957.85,1022.4 915.83,1064.43 890.91,1064.43 796.86,970.38 796.86,834.82 867.37,764.32 867.37,749.69 844.59,726.91
PMIC_1V0 on L5_SIGNAL 3 "PMIC_1V0_L05_P43659" (solid, remove dead copper, pour order 43659): 870.24,617.26 905.28,652.31 948.63,652.3 972.34,628.59 972.34,577.34 942.91,547.91 942.91,486.68 958.76,470.84 958.76,385.09 937.74,364.08 803.76,364.08 777.49,390.34 777.49,536.43 858.33,617.26
5V_IN on Bottom Layer "5V_IN_L08_P43741" (solid, remove dead copper, pour order 43741): 23 vertices, not listed, extent 1265,4.71 1873.56,411.11
GND on Bottom Layer "TOP-No Net 1" (solid, remove dead copper, pour order 43746): 100 vertices, not listed, extent 998.25,1187.43 2140,2187.43
RADAR_1P0_RF2 on Bottom Layer "TOP-No Net 1" (solid, remove dead copper, pour order 43736): 19 vertices, not listed, extent 1176.26,1426.03 1395.23,2037.86
RADAR_1P0_RF1 on Bottom Layer "TOP-No Net 1" (solid, remove dead copper, pour order 43734): 35 vertices, not listed, extent 960.98,1353.71 1196.71,1817.67
RADAR_VOUT_PA on Bottom Layer "TOP-No Net 1" (solid, remove dead copper, pour order 43732): 17 vertices, not listed, extent 1405.12,1497.72 1616.17,1791.79
CONN_5V on Bottom Layer "TOP-No Net 1" (solid, remove dead copper, pour order 43728): 18 vertices, not listed, extent 1612.35,328.64 1881.08,521.43
NetJ6_1 on Bottom Layer "NETJ6_1_L08_P43740" (solid, remove dead copper, pour order 43740): 18 vertices, not listed, extent 578.43,-284.38 962.37,172.78
CB_PMIC_1V2 on Bottom Layer "CB_PMIC_1V2_L06_P2772" (solid, remove dead copper, pour order 43742): 125 vertices, not listed, extent 707.63,190.31 1641,580.6
PMIC_1V2 on Bottom Layer "PMIC_1V2_L08_P43710" (solid, remove dead copper, pour order 43710): 1165.05,152.32 1113.59,152.32 1092.32,131.05 1092.32,101.18 1115.94,77.57 1167.07,77.57 1178.14,88.64 1178.14,139.24
PMIC_1V8 on Bottom Layer "PMIC_1V8_L08_P43700" (solid, remove dead copper, pour order 43700): 1079.54,419.3 1103.92,443.67 1103.92,458.21 1110.39,464.68 1118.64,464.68 1124.55,458.77 1124.55,447.8 1119.01,442.26 1119.01,407.84 1113.58,402.4 1100.34,402.4 1095.94,406.8 1086.01,406.8 1079.54,413.27
RADAR_1V2 on Bottom Layer "RADAR_1V2_L08_P43733" (solid, remove dead copper, pour order 43733): 21 vertices, not listed, extent 597.55,1506.97 809.14,1951.95
RADAR_1V2 on Bottom Layer "RADAR_1V2_L08_P43703" (solid, remove dead copper, pour order 43703): 971.35,1201.34 989.04,1201.34 1000.29,1212.6 1000.29,1229.3 1004.49,1233.49 1025.39,1233.49 1034.55,1224.33 1034.55,1188.24 1018.83,1172.52 971.11,1172.52 966.9,1176.73 966.9,1196.89
RADAR_1V2 on Bottom Layer "RADAR_1V2_L08_P43706" (solid, remove dead copper, pour order 43706): 1093.16,1021.72 1093.16,1082.04 1099.96,1088.84 1148.29,1088.84 1153.05,1084.08 1153.05,1038.42 1141.83,1027.2 1120.11,1027.2 1111.35,1018.44 1096.44,1018.44
GND on Bottom Layer "TOP-No Net 1" (solid, remove dead copper, pour order 43745): 31,2092.43 228,2092.43 300,2164.43 2134,2164.43 2140,2170.43 2140,2365.43 30,2365.43 30,2091.43
GND on Bottom Layer "TOP-No Net 1" (solid, remove dead copper, pour order 43744): 215,241.43 30,241.61 30,2365.43 30.99,2366.43 240,2366.43 240,1370.43 205,1335.43 205,977.29 163.49,935.78 163.49,422.32 215,370.82
GND on Bottom Layer "RADAR_1V8_L01_P-001" (solid, remove dead copper, pour order 43743): 40 vertices, not listed, extent 927,1674.43 1620,2214.43
RADAR_3V3 on Bottom Layer "RADAR_3V3_L06_P386" (solid, remove dead copper, pour order 43739): 44 vertices, not listed, extent 687.41,827.05 1299.98,1270.17
CONN_5V on Bottom Layer "TOP-No Net 1" (solid, remove dead copper, pour order 43738): 29 vertices, not listed, extent 241,1061.43 597.21,1359.64
PMIC_1V0 on Bottom Layer "PMIC_1V0_L06_P428" (solid, remove dead copper, pour order 43737): 19 vertices, not listed, extent 556.54,1070.5 758,1627.61
CB_PMIC_1V0 on Bottom Layer "CB_PMIC_1V0_L06_P422" (solid, remove dead copper, pour order 43735): 26 vertices, not listed, extent 667.13,1670.75 1168.35,2041.75
VCC_3V3 on Bottom Layer "VCC_3V3_L08_P43731" (solid, remove dead copper, pour order 43731): 546.69,305.17 482.11,305.17 431.54,355.74 431.54,469.82 464.17,502.45 609.24,502.45 630.7,480.99 630.7,369.35 566.52,305.17
CB_PMIC_1V0 on Bottom Layer "CB_PMIC_1V0_L06_P424" (solid, remove dead copper, pour order 43730): 19 vertices, not listed, extent 417.63,1372.81 650.33,1615.27
VCC_LD_SW_3V3 on Bottom Layer "TOP-No Net 1" (solid, remove dead copper, pour order 43729): 26 vertices, not listed, extent 706.38,906.43 857.38,1218.27
GND on Bottom Layer "GND_L06_P444" (solid, remove dead copper, pour order 43727): 20 vertices, not listed, extent 830.07,1459.82 1036.67,1703.65
5V_IN_USB on Bottom Layer "5V_IN_USB_L08_P43725" (solid, remove dead copper, pour order 43725): 1648.15,-278.35 1648.15,-239.3 1696.71,-190.74 1905.34,-190.74 1922.68,-208.08 1922.68,-272 1906.32,-288.35 1658.16,-288.35
RADAR_1V8 on Bottom Layer "RADAR_1V8_L08_P43726" (solid, remove dead copper, pour order 43726): 1110.72,770.33 1062.54,770.33 1056.86,764.64 1056.86,747.83 990.93,681.9 990.93,522.33 1034.44,478.82 1074.08,478.82 1083.1,487.84 1083.1,604.97 1106.96,628.83 1106.96,712.97 1115.45,721.46 1115.45,765.6
5V_IN on Bottom Layer "5V_IN_L08_P43723" (solid, remove dead copper, pour order 43723): 578.71,-117.38 717.03,-117.38 728.41,-128.76 728.41,-152.6 695.46,-185.55 695.46,-284.06 578.71,-284.06
PMIC_1V2 on Bottom Layer "PMIC_1V2_L08_P43722" (solid, remove dead copper, pour order 43722): 17 vertices, not listed, extent 691.45,401.54 836.65,558.54
CB_PMIC_1V2 on Bottom Layer "CB_PMIC_1V2_L08_P43724" (solid, remove dead copper, pour order 43724): 573.46,1763.34 589.91,1779.8 589.91,1823.2 635.43,1868.71 635.43,1934.95 613.61,1956.77 526.49,1956.76 498.38,1928.66 498.38,1797.78 532.83,1763.34
CB_PMIC_1V8 on Bottom Layer "CB_PMIC_1V8_L08_P43721" (solid, remove dead copper, pour order 43721): 21 vertices, not listed, extent 975.72,708.76 1194.59,839.36
GND on Bottom Layer "GND_L08_P43720" (solid, remove dead copper, pour order 43720): 21 vertices, not listed, extent 705.91,1859.9 904.01,1997.68
GND on Bottom Layer "GND_L06_P430" (solid, remove dead copper, pour order 43719): 25 vertices, not listed, extent 1038.15,957.76 1213,1127.41
GND on Bottom Layer "GND_L08_P43718" (solid, remove dead copper, pour order 43718): 1249.54,823.94 1325.99,823.94 1339.87,810.06 1339.87,718.57 1302.83,681.54 1232.02,681.54 1220.87,692.68 1220.87,795.27
CB_PMIC_1V0 on Bottom Layer "CB_PMIC_1V0_L06_P2768" (solid, remove dead copper, pour order 43717): 1545.31,541.43 1542.35,541.43 1525.83,524.91 1525.83,479.83 1565.72,439.95 1628.46,439.94 1677.05,488.53 1677.05,521.87 1657.49,541.43
RADAR_3V3 on Bottom Layer "RADAR_3V3_L08_P43716" (solid, remove dead copper, pour order 43716): 1824.61,1105.87 1824.61,1137.08 1859.73,1172.2 1859.73,1217.12 1839.13,1237.73 1839.13,1301.68 1845.28,1307.83 1876.04,1307.83 1895.82,1288.05 1895.82,1256.19 1913.03,1238.98 1913.03,1146.38 1863.3,1096.65 1833.84,1096.65
VCC_3V3 on Bottom Layer "TOP-No Net 1" (solid, remove dead copper, pour order 43715): 1952.26,561.42 1961.43,552.25 1990.49,552.25 1996.71,546.03 1996.71,483.14 1978,464.43 1952.04,464.43 1928.31,488.17 1928.31,499.66 1915.01,512.96 1894.55,512.96 1877.08,530.43 1777,530.43 1777,561.43
GND on Bottom Layer "GND_L08_P43714" (solid, remove dead copper, pour order 43714): 1417.64,1181.22 1417.64,1113.85 1427.51,1103.99 1441.58,1103.99 1452.81,1115.21 1452.81,1127.38 1487.89,1162.46 1545.39,1162.46 1553.98,1171.05 1553.98,1210.18 1537.28,1226.89 1463.31,1226.89
RADAR_1V8 on Bottom Layer "BOTTOM-AR_1V8" (solid, remove dead copper, pour order 43713): 1183.04,1427.35 1183.04,1414.01 1199.19,1397.86 1199.19,1366.43 1192.36,1359.61 1174.72,1359.61 1174.72,1386.64 1121.4,1439.95 1121.4,1516.87 1183.04,1516.87 1183.04,1429.99
5V_IN_USB on Bottom Layer "5V_IN_USB_L08_P43712" (solid, remove dead copper, pour order 43712): 1666.44,220.23 1636.38,190.17 1636.38,158.65 1658.61,136.41 1712.53,136.41 1731.8,155.67 1731.79,201.24 1712.8,220.23
CB_PMIC_1V8 on Bottom Layer "CB_PMIC_1V8_L08_P43711" (solid, remove dead copper, pour order 43711): 1643.89,581.56 1643.89,553.19 1656.68,540.41 1683.56,540.41 1696.25,553.1 1696.25,603.74 1682.41,617.58 1652.69,617.57 1644.47,609.35 1553.4,609.36 1546.67,602.62 1546.67,589.62 1551.72,584.57 1640.88,584.57
PMIC_1V0 on Bottom Layer "PMIC_1V0_L08_P43709" (solid, remove dead copper, pour order 43709): 884.63,603.4 884.63,577.31 892.91,569.02 963.81,569.02 976.31,581.52 976.31,621.56 956.03,641.84 923.07,641.84
GND on Bottom Layer "GND_L08_P43708" (solid, remove dead copper, pour order 43708): 975.14,521.11 988.65,507.61 988.65,471.77 994.8,465.62 1006.27,465.62 1025.86,485.21 1025.86,527.91 1006.22,547.55 1006.22,578.24 1002.3,582.17 980.16,582.17 975.14,577.15
GND on Bottom Layer "GND_L08_P43707" (solid, remove dead copper, pour order 43707): 1020.69,190.86 987.66,190.86 970.67,173.88 970.67,130.44 978.32,122.79 1021.07,122.79 1033.19,134.91 1033.19,178.36
VCC_3V3 on Bottom Layer "VCC_3V3_L08_P43705" (solid, remove dead copper, pour order 43705): 465.74,1033.13 458.09,1025.48 458.09,1009.78 465.84,1002.03 575.16,1002.03 575.16,1033.13
CONN_5V on Bottom Layer "CONN_5V_L08_P43704" (solid, remove dead copper, pour order 43704): 668.21,-84.13 681.85,-84.12 686.38,-79.59 686.38,-71.25 696.78,-60.85 720,-60.85 722.36,-58.49 722.36,-32.62 717.86,-28.12 689.04,-28.12 681.58,-20.66 678.03,-17.11 661.3,-17.11 655.38,-23.02 655.38,-71.3
PMIC_1V2 on Bottom Layer "PMIC_1V2_L08_P43702" (solid, remove dead copper, pour order 43702): 1134.07,211.23 1134.07,235.63 1110.26,259.43 1086.92,259.43 1076.28,248.79 1076.28,231.35 1106.13,201.5 1124.34,201.5
5V_IN on Bottom Layer "5V_IN_L08_P43699" (solid, remove dead copper, pour order 43699): 1079.81,216.18 1089.5,206.49 1095.69,200.05 1095.69,191.21 1084.57,180.09 1057.11,180.09 1051.43,185.77 1051.43,216.88 1060.25,225.7 1070.29,225.7
PMIC_1V0 on Bottom Layer "PMIC_1V0_L08_P43698" (solid, remove dead copper, pour order 43698): 876.66,448.22 876.66,420.56 896.55,400.67 911.73,400.67 919.69,408.62 919.69,420.01 899.93,439.77 899.93,445.6 889.72,455.8 884.25,455.81
PMIC_3V3 on Bottom Layer "PMIC_3V3_L08_P43701" (solid, remove dead copper, pour order 43701): 912.52,36.44 920.36,44.28 920.36,73.1 914.77,78.7 886.7,78.7 879.71,71.7 879.71,42.95 886.22,36.44
5V_IN on Bottom Layer "5V_IN_L08_P43697" (solid, remove dead copper, pour order 43697): 935.79,469.23 913.45,469.23 906.78,462.56 906.78,441.82 922.01,426.59 934.29,426.59 943.38,435.68 943.38,461.65
5V_IN on Bottom Layer "5V_IN_L08_P43696" (solid, remove dead copper, pour order 43696): 1065.52,469.88 1089.92,469.88 1094.53,465.26 1094.53,446.19 1089.35,441 1079.36,431.02 1060.29,431.02 1056.16,435.15 1056.16,460.52
5V_IN on Bottom Layer "5V_IN_L08_P43695" (solid, remove dead copper, pour order 43695): 939.63,221.08 922.83,221.08 912.64,210.9 907.24,205.5 907.24,188.9 913.3,182.84 937.84,182.84 946.5,191.5 946.5,214.21
no net on Bottom Layer "NONET_L08_P43693" (solid, remove dead copper, pour order 43693): 1569.79,-6.89
no net on Bottom Layer "NONET_L08_P43694" (solid, remove dead copper, pour order 43694): 804.19,1139.15
no net on Bottom Solder "RADAR_1V8_L01_P-001" (solid, pour order 43747): 48 vertices, not listed, extent 1068,1195.43 1955,2232.3
CONN_5V on L4_SIGNAL 2 "CONN_5V_L04_P43676" (solid, remove dead copper, pour order 43676): 22 vertices, not listed, extent 1388.84,-101.66 1860.72,535.27
VCC_LD_SW_3V3 on L4_SIGNAL 2 "VCC_LD_SW_3V3_L04_P43678" (solid, remove dead copper, pour order 43678): 826.61,990.49 837.44,979.66 930.65,979.66 990.05,920.27 990.05,583.83 942.18,535.96 942.18,502.93 925.77,486.52 865.94,486.52 813.5,538.95 713.54,538.95 706.94,545.55 706.94,982.46 714.97,990.49
GND on L4_SIGNAL 2 "GND_L04_P43683" (solid, remove dead copper, pour order 43683): 78 vertices, not listed, extent 273.62,-307.72 1388.71,1117.7
PMIC_1V2 on L4_SIGNAL 2 "PMIC_1V2_L04_P43677" (solid, remove dead copper, pour order 43677): 38 vertices, not listed, extent 678.98,78.46 1244.86,516.83
RADAR_3V3 on L4_SIGNAL 2 "RADAR_3V3_L04_P43684" (solid, remove dead copper, pour order 43684): 18 vertices, not listed, extent 788.39,1067.34 2037.57,1708.68
5V_IN on L4_SIGNAL 2 "5V_IN_L04_P43682" (solid, remove dead copper, pour order 43682): 29 vertices, not listed, extent 1546.44,-281.93 1963.86,284.3
CB_PMIC_1V0 on L4_SIGNAL 2 "CB_PMIC_1V0_L04_P43680" (solid, remove dead copper, pour order 43680): 434.47,1775.47 560.43,1775.47 647.64,1862.68 767.58,1862.68 828.79,1801.47 828.79,1543.27 721.27,1435.76 600.53,1435.76 560.34,1395.57 416.07,1395.57 400.94,1410.7 400.94,1741.94
5V_IN on L4_SIGNAL 2 "5V_IN_L04_P43681" (solid, remove dead copper, pour order 43681): 27 vertices, not listed, extent 133.29,-286.19 887.24,280.97
PMIC_1V8 on L4_SIGNAL 2 "PMIC_1V8_L04_P43679" (solid, remove dead copper, pour order 43679): 1248.09,667.01 1444.87,470.23 1444.87,387.29 1444.87,343.72 1356.02,254.87 1168.38,254.87 1037.34,385.92 980.94,385.92 948.61,418.25 948.61,533.17 992.02,576.57 992.02,636.86 1022.17,667.01
VCC_3V3 on L4_SIGNAL 2 "VCC_3V3_L04_P43675" (solid, remove dead copper, pour order 43675): 28 vertices, not listed, extent 820.26,-10.94 1308.08,317.12
RADAR_1V2 on L4_SIGNAL 2 "RADAR_1V2_L04_P43674" (solid, remove dead copper, pour order 43674): 1013.51,974.4 1116.92,974.4 1161.23,1018.71 1161.23,1052.08 1161.23,1069.81 1139.09,1091.95 985.01,1091.95 948.19,1128.77 851.6,1128.77 814.78,1091.94 814.78,1027.31 867.69,974.4
PMIC_3V3 on L4_SIGNAL 2 "PMIC_3V3_L04_P43673" (solid, remove dead copper, pour order 43673): 17 vertices, not listed, extent 845.88,35.77 958.85,254.27
CB_PMIC_1V0 on L6_SIGNAL 4 "CB_PMIC_1V0_L06_P43692" (solid, remove dead copper, pour order 43692): 23 vertices, not listed, extent 372.31,440.16 1780.59,2062.92
CONN_5V on L6_SIGNAL 4 "CONN_5V_L06_P43687" (solid, remove dead copper, pour order 43687): 23 vertices, not listed, extent 705.14,-283.5 1414.33,358.14
PMICOUT_3V3 on L6_SIGNAL 4 "PMICOUT_3V3_L06_P43689" (solid, remove dead copper, pour order 43689): 1788.28,475.23 1866.94,553.89 2079.57,553.89 2157.3,476.16 2157.3,-7.63 2057.41,-107.52 1681.52,-107.52 1635.4,-61.4 1635.4,109.01 1698.06,171.67 1788.28,261.89
5V_IN on L6_SIGNAL 4 "5V_IN_L06_P43691" (solid, remove dead copper, pour order 43691): 30 vertices, not listed, extent 29.98,-283.8 1095.63,1210.97
PMIC_1V0 on L6_SIGNAL 4 "PMIC_1V0_L06_P43690" (solid, remove dead copper, pour order 43690): 34 vertices, not listed, extent 427.96,515.02 978.35,1613.68
RADAR_1V8 on L6_SIGNAL 4 "RADAR_1V8_L06_P43688" (solid, remove dead copper, pour order 43688): 23 vertices, not listed, extent 883.8,629.93 1255.75,1534.83
PMICVIO_3V3 on L6_SIGNAL 4 "PMICVIO_3V3_L06_P43686" (solid, remove dead copper, pour order 43686): 17 vertices, not listed, extent 772.65,219.56 1190.94,488.5
VCC_3V3 on L6_SIGNAL 4 "VCC_3V3_L06_P43685" (solid, remove dead copper, pour order 43685): 347.07,1482.73 412,1417.8 412,1394.41 420.32,1386.08 420.32,1173.19 502.41,1091.11 502.41,1027.03 476.08,1000.7 376.25,1000.7 347.25,1029.7 347.25,1175.35 235.53,1287.07 235.53,1459.64 258.62,1482.73
GND on L2_GND "GND_L02_P226" (hatched 90Degree grid 5 track 8, remove dead copper, pour order 43649): 34.96,35.8 583.08,35.8 583.08,-276.77 701.29,-276.63 2135,-276.63 2135.01,2361.43 34.96,2361.42
GND on L7_GND "TOP-No Net 1" (solid, remove dead copper, pour order 43672): 0,172.07 0,39.66 28.97,10.69 544.02,10.69 575.91,-21.2 575.91,-276.57 607.69,-308.34 1082.68,-308.34 2165.35,-308.34 2165.35,2368.81 0,2368.81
